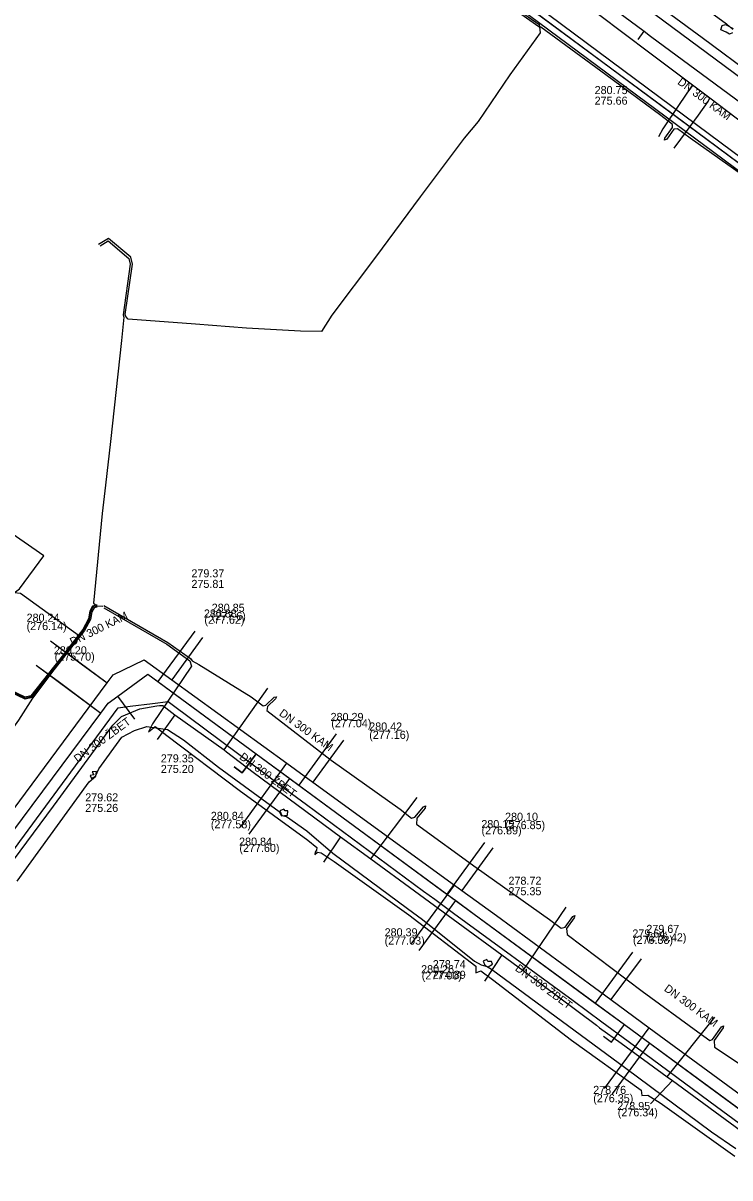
# Model space of a CAD drawing. Extents: x -598233 to -596890, y -1157848 to -1156431.
# Drawn here: x -597667.1 to -597596.8, y -1156857.7 to -1156743 of the extents above; entities that cross this region are included whole.
import ezdxf

# ---------------------------------------------------------------- set-up
doc = ezdxf.new("R2010")
doc.units = 0
for name, color, linetype in [('Vrstva 1', 7, 'Continuous'), ('Vrstva 13', 7, 'Continuous'), ('Vrstva 19', 7, 'Continuous'), ('Vrstva 25', 7, 'Continuous'), ('Vrstva 26', 7, 'Continuous'), ('Vrstva 34', 7, 'Continuous'), ('Vrstva 4', 7, 'Continuous'), ('Vrstva 42', 7, 'Continuous'), ('Vrstva 45', 7, 'Continuous'), ('Vrstva 5', 7, 'Continuous'), ('Vrstva 55', 7, 'Continuous'), ('Vrstva 8', 7, 'Continuous')]:
    doc.layers.add(name, color=color, linetype=linetype)

msp = doc.modelspace()

# ---------------------------------------------------------------- linework, layer by layer
at = {"layer": 'Vrstva 1'}
for p, q in [((-597650.03, -1156803.41), (-597653.7, -1156808.4)), ((-597650.03, -1156803.41), (-597653.7, -1156808.4)), ((-597665.78, -1156806.77), (-597659.36, -1156811.55)), ((-597665.78, -1156806.77), (-597663.47, -1156808.49)), ((-597663.47, -1156808.49), (-597659.36, -1156811.55)), ((-597655.97, -1156812.14), (-597657.66, -1156809.85)), ((-597655.97, -1156812.14), (-597657.66, -1156809.85)), ((-597635.96, -1156813.62), (-597639.7, -1156818.7)), ((-597635.96, -1156813.62), (-597639.7, -1156818.7)), ((-597644.63, -1156823.58), (-597640.57, -1156818.06)), ((-597644.63, -1156823.58), (-597640.57, -1156818.06)), ((-597621.22, -1156824.42), (-597624.97, -1156829.53)), ((-597621.22, -1156824.42), (-597624.97, -1156829.53)), ((-597627.72, -1156835.13), (-597624.08, -1156830.18)), ((-597627.72, -1156835.13), (-597624.08, -1156830.18)), ((-597606.52, -1156835.32), (-597610.22, -1156840.36)), ((-597606.52, -1156835.32), (-597610.22, -1156840.36)), ((-597608.51, -1156849.39), (-597604.8, -1156844.34)), ((-597608.51, -1156849.39), (-597604.8, -1156844.34))]:
    msp.add_line(p, q, dxfattribs=at)
for points in [[(-597606.99, -1156740.07), (-597570.99, -1156766.77)], [(-597658.63, -1156810.57), (-597657.66, -1156809.85), (-597654.7, -1156807.67), (-597643.91, -1156815.6), (-597622.25, -1156831.53), (-597607.32, -1156842.49), (-597600, -1156847.9), (-597589.14, -1156855.89), (-597577.93, -1156864.28), (-597557.49, -1156879.68), (-597556.93, -1156880.1), (-597552.5, -1156878.67), (-597550.53, -1156876.58)], [(-597658.63, -1156810.57), (-597657.66, -1156809.85), (-597654.7, -1156807.67)], [(-597654.7, -1156807.67), (-597653.7, -1156808.4), (-597643.91, -1156815.6), (-597640.57, -1156818.06), (-597639.7, -1156818.7), (-597624.97, -1156829.53), (-597624.08, -1156830.18), (-597622.25, -1156831.53)], [(-597678.25, -1156836.88), (-597677.1, -1156835.34), (-597671.98, -1156828.47), (-597659.36, -1156811.55), (-597658.63, -1156810.57)], [(-597655.97, -1156812.14), (-597657.66, -1156809.85)], [(-597643.91, -1156815.6), (-597645.3, -1156817.49), (-597646.11, -1156816.9)], [(-597646.11, -1156816.9), (-597645.3, -1156817.49), (-597643.91, -1156815.6)], [(-597622.25, -1156831.53), (-597610.22, -1156840.36), (-597607.32, -1156842.49), (-597604.8, -1156844.34), (-597595.19, -1156851.4), (-597591.04, -1156854.44), (-597589.13, -1156855.84)], [(-597609.42, -1156843.66), (-597608.61, -1156844.25), (-597607.32, -1156842.49)], [(-597609.42, -1156843.66), (-597608.61, -1156844.25), (-597607.32, -1156842.49)]]:
    msp.add_lwpolyline(points, dxfattribs=at)
at = {"layer": 'Vrstva 13'}
for points in [[(-597675.31, -1156687.47), (-597673.55, -1156689.12), (-597670.83, -1156691.51), (-597669.97, -1156692.18), (-597669.08, -1156692.84), (-597663.64, -1156696.87), (-597656.87, -1156701.93), (-597651.63, -1156705.85), (-597645.83, -1156710.19), (-597642.69, -1156712.52), (-597636.15, -1156717.38), (-597631.65, -1156720.72), (-597630.71, -1156721.42), (-597623.34, -1156726.88), (-597620.7, -1156728.83), (-597617.1, -1156731.49), (-597610.54, -1156736.34), (-597605.34, -1156740.19), (-597599.6, -1156744.43), (-597589.07, -1156752.22)], [(-597692.5, -1156858.14), (-597681.86, -1156843.92), (-597669.87, -1156827.65), (-597669.39, -1156827.01), (-597667.41, -1156824.32), (-597657.65, -1156811.01), (-597656.45, -1156810.86), (-597654.24, -1156810.58), (-597652.68, -1156810.38), (-597652.13, -1156810.79), (-597642.68, -1156817.84), (-597641.76, -1156818.53), (-597638.93, -1156820.63), (-597627.28, -1156829.24), (-597626.18, -1156830.05), (-597624.3, -1156831.42), (-597612.41, -1156840.12), (-597609.56, -1156842.22), (-597606.96, -1156844.15), (-597598.18, -1156850.63), (-597594.8, -1156853.14)]]:
    msp.add_lwpolyline(points, dxfattribs=at)
at = {"layer": 'Vrstva 19'}
for points in [[(-597609.91, -1156742.08), (-597604.79, -1156745.93), (-597600.57, -1156749.13), (-597598.84, -1156750.42), (-597595.39, -1156753.01)], [(-597600.57, -1156749.13), (-597600.76, -1156749.41), (-597601.89, -1156751.08), (-597603.52, -1156753.5), (-597603.94, -1156754.29)], [(-597598.84, -1156750.42), (-597599.05, -1156750.77), (-597600.01, -1156752.12), (-597600.83, -1156753.25), (-597601.76, -1156754.53), (-597602.42, -1156755.42)], [(-597647.12, -1156815.2), (-597642.76, -1156809.07)], [(-597674.79, -1156835.24), (-597664.08, -1156820.8), (-597658.16, -1156812.76), (-597657.3, -1156811.89), (-597655.47, -1156811.14), (-597653.8, -1156810.84), (-597653.53, -1156810.81), (-597653.19, -1156810.79), (-597652, -1156811.71), (-597647.12, -1156815.2), (-597646.86, -1156815.39), (-597644.22, -1156817.43), (-597635.54, -1156823.83), (-597632.53, -1156826.03), (-597619.52, -1156835.56), (-597617.4, -1156837.12), (-597610.1, -1156842.56), (-597609.79, -1156842.83), (-597607.66, -1156844.34), (-597603.09, -1156847.68), (-597602.54, -1156848.07), (-597587.85, -1156858.85)], [(-597652, -1156811.71), (-597653.75, -1156814.16)], [(-597632.53, -1156826.03), (-597627.93, -1156819.94)], [(-597635.54, -1156823.83), (-597637.23, -1156826.35)], [(-597617.4, -1156837.12), (-597613.12, -1156830.85)], [(-597619.52, -1156835.56), (-597621.23, -1156838.18)], [(-597603.09, -1156847.68), (-597598.33, -1156841.76)], [(-597602.54, -1156848.07), (-597604.73, -1156850.38)]]:
    msp.add_lwpolyline(points, dxfattribs=at)
at = {"layer": 'Vrstva 25'}
msp.add_lwpolyline([(-597492.94, -1156832.97), (-597503.43, -1156825.14), (-597515.31, -1156816.32), (-597531.3, -1156804.51), (-597548.58, -1156791.84), (-597578.92, -1156769.56), (-597598.07, -1156755.35), (-597616.4, -1156741.77), (-597633.98, -1156728.85)], dxfattribs=at)
at = {"layer": 'Vrstva 26'}
for points in [[(-597493.69, -1156833.15), (-597503.78, -1156825.62), (-597515.67, -1156816.8), (-597531.65, -1156805), (-597548.93, -1156792.32), (-597579.28, -1156770.04), (-597598.43, -1156755.83), (-597616.75, -1156742.25), (-597634.34, -1156729.34)], [(-597633.23, -1156728.66), (-597616.04, -1156741.28), (-597597.71, -1156754.87), (-597578.56, -1156769.08), (-597548.22, -1156791.36), (-597530.94, -1156804.03), (-597514.95, -1156815.83), (-597503.07, -1156824.65), (-597492.58, -1156832.49)]]:
    msp.add_lwpolyline(points, dxfattribs=at)
at = {"layer": 'Vrstva 34'}
msp.add_line((-597659.15, -1156800.94), (-597659.73, -1156800.92), dxfattribs=at)
msp.add_lwpolyline([(-597680.84, -1156804.07), (-597675.74, -1156805.84), (-597666.88, -1156810.07), (-597666.26, -1156809.91), (-597663.37, -1156806.25), (-597661.06, -1156803.29), (-597660.48, -1156802.22), (-597660.34, -1156801.46), (-597660.11, -1156801), (-597659.72, -1156800.91)], dxfattribs=at)
at = {"layer": 'Vrstva 42'}
for points in [[(-597580.61, -1156768.3), (-597603.52, -1156751.29), (-597622.15, -1156737.48)], [(-597620.17, -1156740.03), (-597615.81, -1156743.13), (-597615.78, -1156743.35), (-597615.71, -1156743.96), (-597618.72, -1156748.13), (-597621.87, -1156752.77)], [(-597592.74, -1156760.11), (-597600.8, -1156754.43), (-597602.04, -1156753.49), (-597602.41, -1156753.51), (-597603.13, -1156754.53), (-597603.33, -1156754.63), (-597603.3, -1156754.41), (-597602.55, -1156753.36), (-597602.56, -1156753.06), (-597603.71, -1156752.18), (-597609.19, -1156748.12), (-597615.63, -1156743.38), (-597615.78, -1156743.35), (-597615.85, -1156743.34), (-597620.29, -1156740.19)], [(-597621.87, -1156752.77), (-597623.25, -1156754.41), (-597627.64, -1156760.26), (-597632.05, -1156766.23), (-597636.41, -1156772.01), (-597637.44, -1156773.63), (-597639.53, -1156773.58), (-597644.88, -1156773.3), (-597649.96, -1156772.9), (-597656.65, -1156772.39), (-597656.88, -1156772.13), (-597656.94, -1156771.94), (-597656.23, -1156766.94), (-597656.39, -1156766.25), (-597658.61, -1156764.39), (-597659.59, -1156764.99)], [(-597659.43, -1156765.13), (-597658.63, -1156764.63), (-597656.57, -1156766.37), (-597656.43, -1156766.94), (-597657.14, -1156771.96), (-597657.07, -1156772.21), (-597657.3, -1156774.54), (-597658.41, -1156784.57), (-597658.89, -1156788.89), (-597659.23, -1156791.72), (-597660.08, -1156800.63), (-597659.82, -1156800.83), (-597659.72, -1156800.91)], [(-597659.71, -1156800.81), (-597659.82, -1156800.83), (-597660.18, -1156800.91), (-597660.44, -1156801.43), (-597660.58, -1156802.19), (-597661.14, -1156803.24), (-597663.45, -1156806.19), (-597666.32, -1156809.82), (-597666.87, -1156809.96), (-597675.7, -1156805.75), (-597680.8, -1156803.98), (-597681.61, -1156803.67), (-597686.22, -1156800.13), (-597688.5, -1156799.14), (-597688.8, -1156798.65), (-597688.81, -1156798.59)], [(-597659.73, -1156801.01), (-597660.04, -1156801.09), (-597660.24, -1156801.49), (-597660.38, -1156802.25), (-597660.98, -1156803.34), (-597663.29, -1156806.31), (-597666.2, -1156810), (-597666.89, -1156810.18), (-597675.78, -1156805.93)], [(-597659.07, -1156800.87), (-597652.7, -1156804.54), (-597650.45, -1156806.13), (-597650.28, -1156806.34), (-597649.61, -1156806.71), (-597644.42, -1156809.94), (-597643.24, -1156810.82), (-597642.96, -1156810.77), (-597642.12, -1156809.98), (-597641.91, -1156809.92), (-597641.99, -1156810.13), (-597642.8, -1156810.9), (-597642.85, -1156811.29), (-597636.47, -1156816.23), (-597629.62, -1156821.1), (-597628.49, -1156822), (-597628.14, -1156821.89), (-597627.29, -1156820.87), (-597627.09, -1156820.78), (-597627.14, -1156821), (-597627.97, -1156822), (-597627.98, -1156822.57), (-597622.07, -1156826.88), (-597614.79, -1156832.05), (-597613.63, -1156832.93), (-597613.23, -1156832.82), (-597612.47, -1156831.76), (-597612.27, -1156831.66), (-597612.31, -1156831.88), (-597613.07, -1156832.94), (-597613.03, -1156833.54), (-597605.56, -1156839.18), (-597600.03, -1156843.22), (-597598.85, -1156844.09), (-597598.57, -1156843.99), (-597597.68, -1156842.72), (-597597.48, -1156842.61), (-597597.51, -1156842.83), (-597598.4, -1156844.09), (-597598.37, -1156844.74), (-597590.24, -1156850.14)], [(-597659.07, -1156801.1), (-597652.8, -1156804.7), (-597650.5, -1156806.34), (-597650.35, -1156806.89), (-597654.24, -1156812.63), (-597654.64, -1156813.4), (-597653.96, -1156812.89), (-597652.79, -1156813.78), (-597645.63, -1156819.2), (-597638.79, -1156824.16), (-597637.91, -1156824.9), (-597637.93, -1156825.17), (-597638.07, -1156825.37), (-597638.1, -1156825.59), (-597637.84, -1156825.38), (-597637.45, -1156825.42), (-597636.18, -1156826.31), (-597628.75, -1156831.6), (-597622.09, -1156836.71), (-597622.09, -1156837.37), (-597621.61, -1156837.17), (-597620.43, -1156838.02), (-597612.59, -1156844.05), (-597605.66, -1156849.01), (-597605.6, -1156849.56), (-597605.01, -1156849.52), (-597603.79, -1156850.29), (-597596.35, -1156855.59)]]:
    msp.add_lwpolyline(points, dxfattribs=at)
at = {"layer": 'Vrstva 45'}
for points in [[(-597667.96, -1156799.59), (-597667.45, -1156799.19), (-597665.04, -1156795.91), (-597674.82, -1156789.12), (-597677.05, -1156792.06), (-597678.02, -1156792.03), (-597682.94, -1156787.96), (-597683.52, -1156786.98), (-597683.99, -1156784.73), (-597691.34, -1156784.1)], [(-597688.99, -1156822.48), (-597689.06, -1156821.69), (-597688.74, -1156818.34), (-597682.49, -1156819.01), (-597672.91, -1156820), (-597672.29, -1156818.92), (-597667.5, -1156812.26), (-597666.11, -1156810.07), (-597661.49, -1156803.9), (-597667.33, -1156799.67), (-597667.96, -1156799.59)]]:
    msp.add_lwpolyline(points, dxfattribs=at)
at = {"layer": 'Vrstva 5'}
for p, q in [((-597605.97, -1156744.6), (-597605.37, -1156743.8)), ((-597649.27, -1156804.03), (-597652.32, -1156808.23)), ((-597649.27, -1156804.03), (-597652.32, -1156808.23)), ((-597664.35, -1156804.37), (-597658.74, -1156808.54)), ((-597664.35, -1156804.37), (-597661.3, -1156806.64)), ((-597658.15, -1156807.75), (-597655.06, -1156806.24)), ((-597661.3, -1156806.64), (-597658.74, -1156808.54)), ((-597635.24, -1156814.23), (-597638.28, -1156818.42)), ((-597635.24, -1156814.23), (-597638.28, -1156818.42)), ((-597645.49, -1156822.9), (-597640.87, -1156816.54)), ((-597645.49, -1156822.9), (-597640.87, -1156816.54)), ((-597620.4, -1156824.93), (-597623.47, -1156829.17)), ((-597620.4, -1156824.93), (-597623.47, -1156829.17)), ((-597628.51, -1156834.51), (-597624.21, -1156828.65)), ((-597628.51, -1156834.51), (-597624.21, -1156828.65)), ((-597605.68, -1156835.96), (-597608.67, -1156840.02)), ((-597605.68, -1156835.96), (-597608.67, -1156840.02)), ((-597609.31, -1156848.86), (-597604.87, -1156842.82)), ((-597609.31, -1156848.86), (-597604.87, -1156842.82))]:
    msp.add_line(p, q, dxfattribs=at)
for points in [[(-597638.86, -1156718.94), (-597634.98, -1156721.82), (-597628.49, -1156726.64), (-597621.99, -1156731.46), (-597615.48, -1156736.29), (-597605.37, -1156743.8), (-597604.73, -1156744.27)], [(-597604.73, -1156744.27), (-597591.87, -1156753.77), (-597587.32, -1156757.14), (-597573.16, -1156767.6), (-597570.4, -1156769.64), (-597569.59, -1156770.24), (-597569.01, -1156770.67)], [(-597655.06, -1156806.24), (-597652.32, -1156808.23), (-597640.87, -1156816.54), (-597638.28, -1156818.42), (-597624.21, -1156828.65), (-597623.47, -1156829.17), (-597620.05, -1156831.65)], [(-597674.04, -1156829.15), (-597672.46, -1156827.02), (-597658.74, -1156808.54), (-597658.15, -1156807.75)], [(-597620.05, -1156831.65), (-597608.67, -1156840.02), (-597604.87, -1156842.82), (-597593.72, -1156851.01), (-597591.19, -1156852.88), (-597585.23, -1156857.27)]]:
    msp.add_lwpolyline(points, dxfattribs=at)
at = {"layer": 'Vrstva 55'}
for points in [[(-597599.99, -1156741), (-597597.17, -1156743.04), (-597596.55, -1156743.62)], [(-597596.59, -1156743.94), (-597596.87, -1156744.08), (-597597.22, -1156743.88), (-597597.74, -1156743.64), (-597597.63, -1156743.22), (-597597.27, -1156743.12), (-597596.51, -1156743.53)], [(-597667.69, -1156828.26), (-597665.59, -1156825.37), (-597660.52, -1156818.38), (-597659.86, -1156817.82), (-597659.79, -1156817.36), (-597660.22, -1156817.38), (-597660.05, -1156817.7), (-597660.41, -1156817.74), (-597660.29, -1156818.06), (-597659.9, -1156817.8), (-597659.56, -1156817.1), (-597657.27, -1156813.95), (-597656.01, -1156813.29), (-597654.79, -1156812.87), (-597652.72, -1156813.19), (-597651.13, -1156814.2), (-597647.67, -1156816.93), (-597641.65, -1156821.33), (-597641.41, -1156821.76), (-597640.8, -1156821.69), (-597640.78, -1156821.27), (-597641.05, -1156821.26), (-597641.17, -1156821.1), (-597641.58, -1156821.27), (-597641.39, -1156821.72), (-597640.9, -1156821.84), (-597638.88, -1156823.25), (-597636.32, -1156825.46), (-597628.87, -1156830.97), (-597627.4, -1156832.05), (-597622.24, -1156836.19), (-597621.56, -1156836.55), (-597620.86, -1156836.77), (-597620.43, -1156836.51), (-597620.55, -1156836.22), (-597620.9, -1156836.24), (-597621.01, -1156836.02), (-597621.35, -1156836.19), (-597621.2, -1156836.61), (-597620.55, -1156836.98), (-597607.18, -1156846.83), (-597598.66, -1156853.17), (-597596.25, -1156854.81)]]:
    msp.add_lwpolyline(points, dxfattribs=at)

# ---------------------------------------------------------------- texts
at = {"layer": 'Vrstva 4'}
for s, p in [('280.88', (-597649.12, -1156802.05)), ('(277.62)', (-597649.07, -1156802.67)), ('280.20', (-597664.03, -1156805.71)), ('(275.70)', (-597663.95, -1156806.33)), ('280.29', (-597636.53, -1156812.33)), ('(277.04)', (-597636.46, -1156812.96)), ('279.35', (-597653.4, -1156816.45)), ('275.20', (-597653.4, -1156817.5)), ('279.62', (-597660.91, -1156820.32)), ('275.26', (-597660.91, -1156821.37)), ('280.15', (-597621.55, -1156822.98)), ('(276.89)', (-597621.53, -1156823.6)), ('280.84', (-597645.62, -1156824.72)), ('(277.60)', (-597645.59, -1156825.35)), ('279.64', (-597606.54, -1156833.85)), ('(276.38)', (-597606.48, -1156834.48)), ('278.74', (-597626.37, -1156836.9)), ('280.26', (-597627.53, -1156837.4)), ('(277.00)', (-597627.47, -1156838.02)), ('274.89', (-597626.37, -1156837.95)), ('278.95', (-597608.04, -1156850.99)), ('(276.34)', (-597607.99, -1156851.62))]:
    msp.add_text(s, height=0.8, dxfattribs=at).set_placement(p)
for rotation, p in [(36.4241, (-597661.67, -1156816.51)), (323.6735, (-597645.66, -1156816.05)), (323.7214, (-597618.26, -1156837.07))]:
    msp.add_text('DN 300 ŽBET', height=0.8, rotation=rotation, dxfattribs=at).set_placement(p)
at = {"layer": 'Vrstva 8'}
for rotation, p in [(323.5326, (-597602.12, -1156748.98)), (26.0435, (-597662.2, -1156804.88)), (324.0281, (-597641.71, -1156811.72)), (323.655, (-597603.45, -1156839.08))]:
    msp.add_text('DN 300 KAM', height=0.8, rotation=rotation, dxfattribs=at).set_placement(p)
for s, p in [('280.75', (-597610.29, -1156750.04)), ('275.66', (-597610.29, -1156751.09)), ('279.37', (-597650.36, -1156798.06)), ('275.81', (-597650.36, -1156799.11)), ('280.24', (-597666.74, -1156802.47)), ('280.85', (-597648.34, -1156801.48)), ('(277.6)', (-597648.34, -1156802.31)), ('(276.14)', (-597666.74, -1156803.3)), ('280.42', (-597632.69, -1156813.28)), ('(277.16)', (-597632.69, -1156814.11)), ('280.84', (-597648.43, -1156822.16)), ('(277.58)', (-597648.43, -1156823)), ('280.10', (-597619.19, -1156822.25)), ('(276.85)', (-597619.19, -1156823.08)), ('278.72', (-597618.85, -1156828.6)), ('275.35', (-597618.85, -1156829.65)), ('279.67', (-597605.15, -1156833.39)), ('280.39', (-597631.16, -1156833.73)), ('(277.03)', (-597631.16, -1156834.56)), ('(276.42)', (-597605.15, -1156834.23)), ('278.76', (-597610.43, -1156849.39)), ('(276.35)', (-597610.43, -1156850.22))]:
    msp.add_text(s, height=0.8, dxfattribs=at).set_placement(p)

doc.saveas('drawing.dxf')
